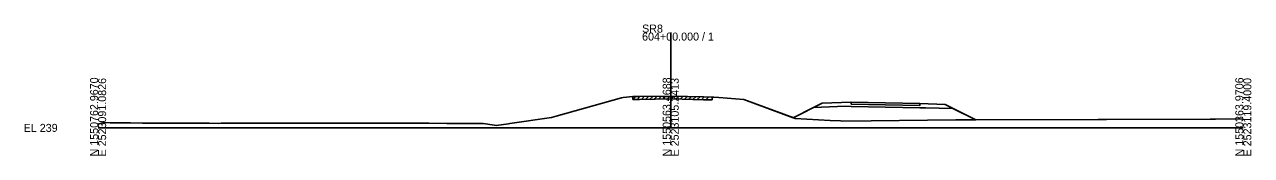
# Model space of a CAD drawing. Extents: x -26 to 2803, y -10 to 19537.
# Drawn here: x -25.7 to 402.8, y 11490.3 to 11536.2 of the extents above; entities that cross this region are included whole.
import ezdxf

# ---------------------------------------------------------------- set-up
doc = ezdxf.new("R2010")
doc.units = 0
for name, color, linetype in [('50', 7, 'Continuous'), ('XS_CELL', 7, 'Continuous'), ('XS_M_MULTI', 7, 'Continuous'), ('XS_M_SHAPES_EARTHWORK', 7, 'Continuous'), ('XS_P_FINISHED_GRADE', 7, 'Continuous'), ('XS_P_SUBGRADE_GRANULAR', 7, 'Continuous'), ('XS_P_SUBGRADE_PAVEMENT', 7, 'Continuous'), ('XS_X_GROUND', 7, 'Continuous')]:
    doc.layers.add(name, color=color, linetype=linetype)

msp = doc.modelspace()

# ---------------------------------------------------------------- linework, layer by layer
at = {"layer": '50'}
for p, q in [((186.76, 11509.96), (187.77, 11510.98)), ((186.76, 11509.96), (186.76, 11510.96)), ((188.26, 11509.98), (189.27, 11510.99)), ((189.76, 11510), (190.77, 11511.01)), ((191.26, 11510.02), (192.27, 11511.03)), ((192.76, 11510.04), (193.77, 11511.05)), ((194.26, 11510.06), (195.27, 11511.07)), ((195.76, 11510.08), (196.77, 11511.09)), ((197.26, 11510.1), (198.27, 11511.11)), ((198.76, 11510.11), (199.77, 11511.13)), ((200.26, 11510.13), (201.24, 11511.11)), ((201.76, 11510.1), (202.73, 11511.07)), ((203.26, 11510.06), (204.23, 11511.04)), ((204.76, 11510.02), (205.73, 11511)), ((206.26, 11509.99), (207.23, 11510.96)), ((207.76, 11509.95), (208.73, 11510.93)), ((209.26, 11509.91), (210.23, 11510.89)), ((210.76, 11509.87), (211.73, 11510.85)), ((212.26, 11509.84), (213.23, 11510.81)), ((214.44, 11510.78), (214.44, 11509.78)), ((186.76, 11509.96), (189.07, 11509.99)), ((189.07, 11509.99), (200, 11510.13)), ((200, 11510.13), (200.32, 11510.13)), ((200.32, 11510.13), (211.42, 11509.86)), ((211.42, 11509.86), (214.44, 11509.78))]:
    msp.add_line(p, q, dxfattribs=at)
at = {"layer": 'XS_CELL'}
for p, q in [((200, 11500), (200, 11533.4)), ((0, 11500), (200, 11500)), ((200, 11500), (400, 11500))]:
    msp.add_line(p, q, dxfattribs=at)
at = {"layer": 'XS_M_MULTI'}
for p, q in [((242.77, 11503.58), (252.86, 11508.62)), ((252.86, 11508.62), (263, 11509.02)), ((263, 11509.02), (275, 11508.78)), ((275, 11508.78), (287, 11508.54)), ((287, 11508.54), (295.81, 11508.19)), ((295.81, 11508.19), (306.53, 11502.84))]:
    msp.add_line(p, q, dxfattribs=at)
for points in [[(0, 11501.31), (2.03, 11501.84), (4.19, 11501.81), (4.62, 11501.81), (9.82, 11501.75), (11.35, 11501.74), (15.45, 11501.7), (18.09, 11501.69), (21.08, 11501.67), (24.81, 11501.66), (26.71, 11501.64), (31.54, 11501.63), (32.34, 11501.63), (36.51, 11501.63), (38.79, 11501.61), (42.22, 11501.59), (43.01, 11501.6), (43.75, 11501.6), (45.72, 11501.62), (47.05, 11501.63), (48.6, 11501.65), (50.13, 11501.66), (51.52, 11501.67), (53.15, 11501.69), (54.45, 11501.7), (56.15, 11501.71), (91.87, 11501.71), (95.47, 11501.69), (99.8, 11501.7), (104.2, 11501.67), (107.67, 11501.67), (112.97, 11501.63), (115.46, 11501.63), (121.79, 11501.57), (123.15, 11501.57), (130.8, 11501.48), (131.17, 11501.48), (134.53, 11501.5), (138.42, 11500.93), (139.05, 11500.84), (143.31, 11501.43), (143.8, 11501.5), (158.37, 11503.6), (159.98, 11504.05), (182.78, 11510.53), (183.44, 11510.6), (186.76, 11510.96), (189.07, 11510.99), (200, 11511.13), (200.32, 11511.13), (211.42, 11510.86), (214.44, 11510.78), (215.03, 11510.74), (216.82, 11510.6), (225.51, 11509.94), (242.77, 11503.58)], [(306.53, 11502.84), (349.34, 11502.97), (350.86, 11502.98), (351.21, 11502.98), (352.21, 11502.98), (388.44, 11503.09), (390.29, 11503.09), (400, 11503.12)]]:
    msp.add_lwpolyline(points, dxfattribs=at)
at = {"layer": 'XS_M_SHAPES_EARTHWORK'}
for points in [[(263, 11507.52), (261, 11507.56), (249.85, 11507.12), (242.77, 11503.58), (242.95, 11503.51), (243.52, 11503.3), (255.66, 11502.63), (259.34, 11502.42), (260.17, 11502.38), (299.55, 11502.82), (303.24, 11502.83), (306.53, 11502.84), (298.58, 11506.81), (289, 11507), (287, 11507.04), (275, 11507.28)], [(263, 11508.27), (275, 11508.03), (287, 11507.79), (287, 11508.54), (295.81, 11508.19), (298.58, 11506.81), (289, 11507), (287, 11507.04), (275, 11507.28), (263, 11507.52), (261, 11507.56), (249.85, 11507.12), (252.86, 11508.62), (263, 11509.02)], [(263, 11508.27), (275, 11508.03), (287, 11507.79), (287, 11508.54), (275, 11508.78), (263, 11509.02)]]:
    msp.add_lwpolyline(points, close=True, dxfattribs=at)
at = {"layer": 'XS_P_FINISHED_GRADE'}
for p, q in [((252.86, 11508.62), (242.77, 11503.58)), ((263, 11509.02), (252.86, 11508.62)), ((263, 11509.02), (275, 11508.78)), ((275, 11508.78), (287, 11508.54)), ((287, 11508.54), (295.81, 11508.19)), ((295.81, 11508.19), (306.53, 11502.84))]:
    msp.add_line(p, q, dxfattribs=at)
at = {"layer": 'XS_P_SUBGRADE_GRANULAR'}
for p, q in [((261, 11507.56), (249.85, 11507.12)), ((263, 11507.52), (261, 11507.56)), ((263, 11507.52), (275, 11507.28)), ((275, 11507.28), (287, 11507.04)), ((287, 11507.04), (289, 11507)), ((289, 11507), (298.58, 11506.81))]:
    msp.add_line(p, q, dxfattribs=at)
at = {"layer": 'XS_P_SUBGRADE_PAVEMENT'}
for p, q in [((263, 11508.27), (263, 11509.02)), ((263, 11508.27), (275, 11508.03)), ((275, 11508.03), (287, 11507.79)), ((287, 11507.79), (287, 11508.54))]:
    msp.add_line(p, q, dxfattribs=at)
at = {"layer": 'XS_X_GROUND'}
msp.add_lwpolyline([(0, 11501.31), (2.03, 11501.84), (4.19, 11501.81), (4.62, 11501.81), (9.82, 11501.75), (11.35, 11501.74), (15.45, 11501.7), (18.09, 11501.69), (21.08, 11501.67), (24.81, 11501.66), (26.71, 11501.64), (31.54, 11501.63), (32.34, 11501.63), (36.51, 11501.63), (38.79, 11501.61), (42.22, 11501.59), (43.01, 11501.6), (43.75, 11501.6), (45.72, 11501.62), (47.05, 11501.63), (48.6, 11501.65), (50.13, 11501.66), (51.52, 11501.67), (53.15, 11501.69), (54.45, 11501.7), (56.15, 11501.71), (91.87, 11501.71), (95.47, 11501.69), (99.8, 11501.7), (104.2, 11501.67), (107.67, 11501.67), (112.97, 11501.63), (115.46, 11501.63), (121.79, 11501.57), (123.15, 11501.57), (130.8, 11501.48), (131.17, 11501.48), (134.53, 11501.5), (138.42, 11500.93), (139.05, 11500.84), (143.31, 11501.43), (143.8, 11501.5), (158.37, 11503.6), (159.98, 11504.05), (182.78, 11510.53), (183.44, 11510.6), (186.76, 11510.96), (189.07, 11510.99), (200, 11511.13), (200.32, 11511.13), (211.42, 11510.86), (214.44, 11510.78), (215.03, 11510.74), (216.82, 11510.6), (225.51, 11509.94), (242.95, 11503.51), (243.52, 11503.3), (255.66, 11502.63), (259.34, 11502.42), (260.17, 11502.38), (299.55, 11502.82), (303.24, 11502.83), (349.34, 11502.97), (350.86, 11502.98), (351.21, 11502.98), (352.21, 11502.98), (388.44, 11503.09), (390.29, 11503.09), (400, 11503.12)], dxfattribs=at)

# ---------------------------------------------------------------- texts
at = {"layer": 'XS_CELL'}
for s, p in [('SR8', (190, 11533.4)), ('604+00.000 / 1', (190, 11530.6)), ('EL 239', (-26, 11498.6))]:
    msp.add_text(s, height=2.8, dxfattribs=at).set_placement(p)
for s, p in [('N 1550762.9670', (0, 11490)), ('E 2523091.0826', (2.8, 11490)), ('N 1550563.4688', (200, 11490)), ('E 2523105.2413', (202.8, 11490)), ('N 1550363.9706', (400, 11490)), ('E 2523119.4000', (402.8, 11490))]:
    msp.add_text(s, height=2.8, rotation=90, dxfattribs=at).set_placement(p)

doc.saveas('drawing.dxf')
